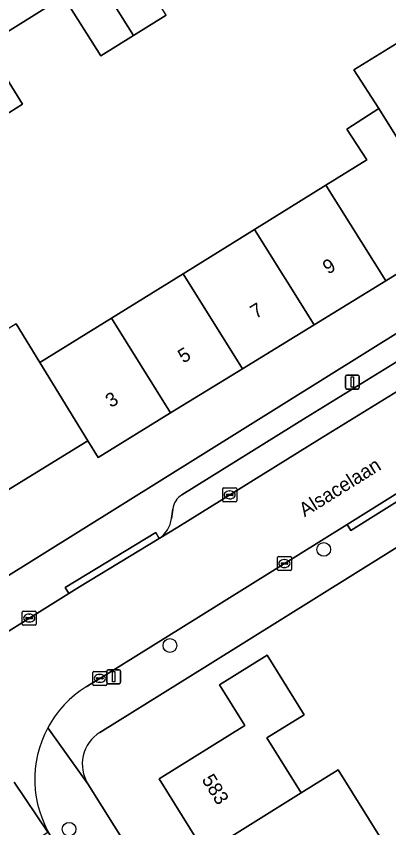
# Model space of a CAD drawing. Extents: x 157767 to 159172, y 387839 to 389425.
# Drawn here: x 158720.1 to 158746.7, y 388133.7 to 388191.6 of the extents above; entities that cross this region are included whole.
import ezdxf

# ---------------------------------------------------------------- set-up
doc = ezdxf.new("R2010")
doc.units = 0
for name, color, linetype in [('IMGEO_Boom', 7, 'Continuous'), ('IMGEO_Erf', 7, 'Continuous'), ('IMGEO_Kolk', 7, 'Continuous'), ('IMGEO_Lichtmast', 7, 'Continuous'), ('IMGEO_Muur', 7, 'Continuous'), ('IMGEO_Openbare_ruimte_label', 7, 'Continuous'), ('IMGEO_Pand', 7, 'Continuous'), ('IMGEO_Pand_nummerreeks', 7, 'Continuous'), ('IMGEO_Parkeervlak_open', 7, 'Continuous'), ('IMGEO_Rijbaan_lokaal_gesloten', 7, 'Continuous'), ('IMGEO_Rijbaan_lokaal_open', 7, 'Continuous'), ('IMGEO_Voetpad_open', 7, 'Continuous')]:
    doc.layers.add(name, color=color, linetype=linetype)

msp = doc.modelspace()

# ---------------------------------------------------------------- linework, layer by layer
at = {"layer": 'IMGEO_Boom'}
for centre in [(158742.03, 388153.561), (158731.046, 388146.702), (158723.845, 388133.586)]:
    msp.add_circle(centre, 0.489, dxfattribs=at)
at = {"layer": 'IMGEO_Erf'}
for points in [[(158761.692, 388194.688), (158765.881, 388187.864), (158760.624, 388184.637), (158755.413, 388181.438), (158752.713, 388179.781), (158754.565, 388176.764), (158752.076, 388175.236), (158748.692, 388173.159), (158748.271, 388173.845), (158746.449, 388172.727), (158741.336, 388169.588), (158736.223, 388166.45), (158731.091, 388163.3), (158725.924, 388160.128), (158725.19, 388161.323), (158725.067, 388161.247), (158716.251, 388155.836)], [(158743.681, 388183.556), (158745.961, 388185.032), (158744.167, 388187.803), (158749.433, 388191.036), (158751.173, 388188.231), (158756.335, 388191.4), (158754.508, 388194.376)], [(158730.775, 388191.695), (158728.443, 388190.242), (158726.101, 388188.784), (158723.453, 388193.037), (158717.902, 388189.558), (158720.525, 388185.346), (158718.236, 388183.92)], [(158720.07, 388169.662), (158721.758, 388166.913), (158726.866, 388170.077), (158731.981, 388173.244), (158737.082, 388176.403), (158742.182, 388179.562), (158745.097, 388181.367), (158743.681, 388183.556)], [(158650.367, 388165.452), (158650.337, 388165.203), (158715.951, 388149.492), (158768.176, 388182.052)], [(158771.779, 388169.011), (158765.822, 388165.297), (158752.075, 388156.726), (158733.718, 388145.281), (158728.372, 388141.947), (158726.036, 388140.491)], [(158733.566, 388131.912), (158730.278, 388137.186), (158736.388, 388140.995), (158734.585, 388143.889), (158737.98, 388146.006), (158740.626, 388141.763), (158737.975, 388140.111), (158740.422, 388136.185), (158743.064, 388137.832), (158746.254, 388132.715)], [(158725.193, 388136.821), (158765.78, 388072.075)]]:
    msp.add_lwpolyline(points, dxfattribs=at)
msp.add_arc((158727.448, 388138.235), 2.661, 122.03762, 212.08947, dxfattribs=at)
at = {"layer": 'IMGEO_Kolk'}
for p, q in [((158734.811, 388157.027), (158734.811, 388157.879)), ((158734.886, 388157.953), (158735.738, 388157.953)), ((158735.07, 388157.447), (158735.07, 388157.459)), ((158735.113, 388157.496), (158735.511, 388157.496)), ((158735.299, 388157.733), (158735.324, 388157.733)), ((158735.554, 388157.459), (158735.554, 388157.447)), ((158735.812, 388157.879), (158735.812, 388157.027)), ((158735.738, 388156.953), (158734.886, 388156.953)), ((158735.508, 388157.41), (158735.11, 388157.41)), ((158735.322, 388157.173), (158735.297, 388157.173)), ((158738.717, 388152.124), (158738.717, 388152.976)), ((158738.792, 388153.05), (158739.644, 388153.05)), ((158739.205, 388152.83), (158739.23, 388152.83)), ((158739.718, 388152.976), (158739.718, 388152.124)), ((158738.976, 388152.544), (158738.976, 388152.556)), ((158739.414, 388152.507), (158739.016, 388152.507)), ((158739.019, 388152.593), (158739.417, 388152.593)), ((158739.228, 388152.27), (158739.203, 388152.27)), ((158739.46, 388152.556), (158739.46, 388152.544)), ((158739.644, 388152.05), (158738.792, 388152.05)), ((158720.503, 388148.234), (158720.503, 388149.086)), ((158720.578, 388149.16), (158721.43, 388149.16)), ((158720.991, 388148.94), (158721.016, 388148.94)), ((158721.504, 388149.086), (158721.504, 388148.234)), ((158721.43, 388148.16), (158720.578, 388148.16)), ((158720.762, 388148.654), (158720.762, 388148.666)), ((158721.2, 388148.617), (158720.802, 388148.617)), ((158720.805, 388148.703), (158721.203, 388148.703)), ((158721.014, 388148.38), (158720.989, 388148.38)), ((158721.246, 388148.666), (158721.246, 388148.654)), ((158725.539, 388143.928), (158725.539, 388144.78)), ((158725.614, 388144.854), (158726.466, 388144.854)), ((158726.54, 388144.78), (158726.54, 388143.928)), ((158725.798, 388144.348), (158725.798, 388144.36)), ((158726.236, 388144.311), (158725.838, 388144.311)), ((158725.841, 388144.397), (158726.239, 388144.397)), ((158726.027, 388144.634), (158726.052, 388144.634)), ((158726.282, 388144.36), (158726.282, 388144.348)), ((158726.466, 388143.854), (158725.614, 388143.854)), ((158726.05, 388144.074), (158726.025, 388144.074))]:
    msp.add_line(p, q, dxfattribs=at)
for points in [[(158734.811, 388157.027), (158734.811, 388157.879)], [(158734.886, 388157.953), (158735.738, 388157.953)], [(158735.812, 388157.879), (158735.812, 388157.027)], [(158735.738, 388156.953), (158734.886, 388156.953)], [(158738.717, 388152.124), (158738.717, 388152.976)], [(158738.792, 388153.05), (158739.644, 388153.05)], [(158739.718, 388152.976), (158739.718, 388152.124)], [(158739.644, 388152.05), (158738.792, 388152.05)], [(158720.503, 388148.234), (158720.503, 388149.086)], [(158720.578, 388149.16), (158721.43, 388149.16)], [(158721.504, 388149.086), (158721.504, 388148.234)], [(158721.43, 388148.16), (158720.578, 388148.16)], [(158725.539, 388143.928), (158725.539, 388144.78)], [(158725.614, 388144.854), (158726.466, 388144.854)], [(158726.54, 388144.78), (158726.54, 388143.928)], [(158726.466, 388143.854), (158725.614, 388143.854)]]:
    msp.add_lwpolyline(points, dxfattribs=at)
for centre, radius, start, end in [((158734.888, 388157.877), 0.0765, 91.55205, 178.44795), ((158734.888, 388157.877), 0.0765, 91.55205, 178.44795), ((158735.11, 388157.456), 0.0403, 85.87752, 175.75265), ((158735.107, 388157.446), 0.0366, 178.93798, 274.71019), ((158735.511, 388157.453), 0.043, 264.86636, 352.45326), ((158735.515, 388157.458), 0.0386, 1.73085, 96.63898), ((158735.736, 388157.877), 0.0765, 1.55205, 88.44795), ((158735.736, 388157.877), 0.0765, 1.55205, 88.44795), ((158734.888, 388157.029), 0.0765, 181.55205, 268.44795), ((158734.888, 388157.029), 0.0765, 181.55205, 268.44795), ((158735.736, 388157.029), 0.0765, 271.55205, 358.44795), ((158735.736, 388157.029), 0.0765, 271.55205, 358.44795), ((158738.794, 388152.974), 0.0765, 91.55205, 178.44795), ((158738.794, 388152.974), 0.0765, 91.55205, 178.44795), ((158739.642, 388152.974), 0.0765, 1.55205, 88.44795), ((158739.642, 388152.974), 0.0765, 1.55205, 88.44795), ((158739.016, 388152.553), 0.0403, 85.87752, 175.75265), ((158739.013, 388152.543), 0.0366, 178.93798, 274.71019), ((158739.417, 388152.55), 0.043, 264.86636, 352.45326), ((158739.421, 388152.555), 0.0386, 1.73085, 96.63898), ((158738.794, 388152.126), 0.0765, 181.55205, 268.44795), ((158738.794, 388152.126), 0.0765, 181.55205, 268.44795), ((158739.642, 388152.126), 0.0765, 271.55205, 358.44795), ((158739.642, 388152.126), 0.0765, 271.55205, 358.44795), ((158720.58, 388149.084), 0.0765, 91.55205, 178.44795), ((158720.58, 388149.084), 0.0765, 91.55205, 178.44795), ((158721.428, 388149.084), 0.0765, 1.55205, 88.44795), ((158721.428, 388149.084), 0.0765, 1.55205, 88.44795), ((158720.58, 388148.236), 0.0765, 181.55205, 268.44795), ((158720.58, 388148.236), 0.0765, 181.55205, 268.44795), ((158720.802, 388148.663), 0.0403, 85.87752, 175.75265), ((158720.799, 388148.653), 0.0366, 178.93798, 274.71019), ((158721.203, 388148.66), 0.043, 264.86636, 352.45326), ((158721.207, 388148.665), 0.0386, 1.73085, 96.63898), ((158721.428, 388148.236), 0.0765, 271.55205, 358.44795), ((158721.428, 388148.236), 0.0765, 271.55205, 358.44795), ((158725.616, 388144.778), 0.0765, 91.55205, 178.44795), ((158725.616, 388144.778), 0.0765, 91.55205, 178.44795), ((158726.464, 388144.778), 0.0765, 1.55205, 88.44795), ((158726.464, 388144.778), 0.0765, 1.55205, 88.44795), ((158725.838, 388144.357), 0.0403, 85.87752, 175.75265), ((158725.835, 388144.347), 0.0366, 178.93798, 274.71019), ((158726.239, 388144.354), 0.043, 264.86636, 352.45326), ((158726.243, 388144.359), 0.0386, 1.73085, 96.63898), ((158725.616, 388143.93), 0.0765, 181.55205, 268.44795), ((158725.616, 388143.93), 0.0765, 181.55205, 268.44795), ((158726.464, 388143.93), 0.0765, 271.55205, 358.44795), ((158726.464, 388143.93), 0.0765, 271.55205, 358.44795)]:
    msp.add_arc(centre, radius, start, end, dxfattribs=at)
for centre, major_axis, ratio, start_param, end_param in [((158735.298, 388157.453), (-0.387, 0.002), 0.722429, 4.712389, 7.853982), ((158735.323, 388157.453), (-0.39, 0.002), 0.717154, 1.570796, 4.712389), ((158739.204, 388152.55), (-0.387, 0.002), 0.722429, 4.712389, 7.853982), ((158739.229, 388152.55), (-0.39, 0.002), 0.717154, 1.570796, 4.712389), ((158720.99, 388148.66), (-0.387, 0.002), 0.722429, 4.712389, 7.853982), ((158721.015, 388148.66), (-0.39, 0.002), 0.717154, 1.570796, 4.712389), ((158726.026, 388144.354), (-0.387, 0.002), 0.722429, 4.712389, 7.853982), ((158726.051, 388144.354), (-0.39, 0.002), 0.717154, 1.570796, 4.712389)]:
    msp.add_ellipse(centre, major_axis=major_axis, ratio=ratio, start_param=start_param, end_param=end_param, dxfattribs=at)
at = {"layer": 'IMGEO_Lichtmast'}
for p, q in [((158743.569, 388165.107), (158743.569, 388165.907)), ((158743.569, 388165.907), (158743.569, 388165.107)), ((158743.669, 388166.007), (158744.459, 388166.007)), ((158744.459, 388166.007), (158743.669, 388166.007)), ((158744.559, 388165.907), (158744.559, 388165.107)), ((158744.559, 388165.107), (158744.559, 388165.907)), ((158744.459, 388165.007), (158743.669, 388165.007)), ((158743.669, 388165.007), (158744.459, 388165.007)), ((158726.536, 388144.076), (158726.536, 388144.876)), ((158726.536, 388144.876), (158726.536, 388144.076)), ((158726.636, 388144.976), (158727.426, 388144.976)), ((158727.426, 388144.976), (158726.636, 388144.976)), ((158727.526, 388144.876), (158727.526, 388144.076)), ((158727.526, 388144.076), (158727.526, 388144.876)), ((158727.426, 388143.976), (158726.636, 388143.976)), ((158726.636, 388143.976), (158727.426, 388143.976))]:
    msp.add_line(p, q, dxfattribs=at)
for points in [[(158743.989, 388165.882), (158744.139, 388165.882), (158744.139, 388165.132), (158743.989, 388165.132), (158743.989, 388165.882)], [(158726.956, 388144.851), (158727.106, 388144.851), (158727.106, 388144.101), (158726.956, 388144.101), (158726.956, 388144.851)]]:
    msp.add_lwpolyline(points, dxfattribs=at)
for centre, start, end in [((158743.669, 388165.907), 90, 180), ((158743.669, 388165.907), 90, 180), ((158744.459, 388165.907), 0, 90), ((158744.459, 388165.907), 360, 90), ((158743.669, 388165.107), 180, 270), ((158743.669, 388165.107), 180, 270), ((158744.459, 388165.107), 270, 0), ((158744.459, 388165.107), 270, 0), ((158726.636, 388144.876), 90, 180), ((158726.636, 388144.876), 90, 180), ((158727.426, 388144.876), 0, 90), ((158727.426, 388144.876), 360, 90), ((158726.636, 388144.076), 180, 270), ((158726.636, 388144.076), 180, 270), ((158727.426, 388144.076), 270, 0), ((158727.426, 388144.076), 270, 0)]:
    msp.add_arc(centre, 0.1, start, end, dxfattribs=at)
at = {"layer": 'IMGEO_Muur'}
msp.add_lwpolyline([(158733.718, 388145.281), (158728.372, 388141.947)], dxfattribs=at)
at = {"layer": 'IMGEO_Pand'}
for points in [[(158728.443, 388190.242), (158730.775, 388191.695), (158728.127, 388195.948), (158725.79, 388194.492)], [(158728.443, 388190.242), (158725.79, 388194.492), (158723.453, 388193.037), (158726.101, 388188.784)], [(158745.961, 388185.032), (158752.076, 388175.236), (158754.565, 388176.764), (158752.713, 388179.781), (158755.413, 388181.438), (158751.173, 388188.231), (158749.433, 388191.036), (158744.167, 388187.803)], [(158715.611, 388188.131), (158718.236, 388183.92), (158720.525, 388185.346), (158717.902, 388189.558)], [(158745.961, 388185.032), (158743.681, 388183.556), (158745.097, 388181.367), (158742.182, 388179.562), (158746.449, 388172.727), (158748.271, 388173.845), (158748.692, 388173.159), (158752.076, 388175.236)], [(158746.449, 388172.727), (158742.182, 388179.562), (158737.082, 388176.403), (158741.336, 388169.588)], [(158737.082, 388176.403), (158731.981, 388173.244), (158736.223, 388166.45), (158741.336, 388169.588)], [(158726.866, 388170.077), (158731.091, 388163.3), (158736.223, 388166.45), (158731.981, 388173.244)], [(158721.758, 388166.913), (158720.07, 388169.662), (158714.573, 388166.287), (158713.927, 388167.33), (158711.467, 388165.807), (158712.066, 388162.649), (158715.824, 388156.53), (158716.251, 388155.836), (158725.067, 388161.247), (158725.19, 388161.323)], [(158726.866, 388170.077), (158721.758, 388166.913), (158725.19, 388161.323), (158725.924, 388160.128), (158731.091, 388163.3)], [(158740.422, 388136.185), (158737.975, 388140.111), (158740.626, 388141.763), (158737.98, 388146.006), (158734.585, 388143.889), (158736.388, 388140.995), (158730.278, 388137.186), (158733.566, 388131.912)], [(158740.422, 388136.185), (158733.566, 388131.912), (158736.756, 388126.794), (158743.612, 388131.068), (158746.254, 388132.715), (158743.064, 388137.832)]]:
    msp.add_lwpolyline(points, close=True, dxfattribs=at)
at = {"layer": 'IMGEO_Parkeervlak_open'}
for points in [[(158730.286, 388154.349), (158731.615, 388155.157), (158741.723, 388161.435), (158752.849, 388168.293), (158761.897, 388173.962), (158770.871, 388179.63)], [(158767.748, 388179.761), (158760.94, 388175.488), (158751.898, 388169.823), (158740.775, 388162.967), (158731.897, 388157.453)], [(158731.247, 388156.441), (158731.16, 388155.759)]]:
    msp.add_lwpolyline(points, dxfattribs=at)
for centre, radius, start, end in [((158732.639, 388156.262), 1.404, 121.91626, 172.65908), ((158729.176, 388156.013), 2, 303.70666, 352.70725)]:
    msp.add_arc(centre, radius, start, end, dxfattribs=at)
at = {"layer": 'IMGEO_Rijbaan_lokaal_gesloten'}
msp.add_lwpolyline([(158717.852, 388129.025), (158725.178, 388117.248), (158731.411, 388107.326), (158740.295, 388093.103), (158749.242, 388078.803), (158749.797, 388077.971), (158750.922, 388076.09), (158754.085, 388078.005), (158751.334, 388082.198), (158745.833, 388091.038), (158737.528, 388104.244), (158727.681, 388119.9), (158720.109, 388131.939), (158722.336, 388133.375), (158719.936, 388136.946)], dxfattribs=at)
at = {"layer": 'IMGEO_Rijbaan_lokaal_open'}
for points in [[(158717.902, 388189.558), (158723.453, 388193.037)], [(158776.519, 388171.716), (158771.15, 388179.789), (158770.871, 388179.63), (158761.897, 388173.962), (158752.849, 388168.293), (158741.723, 388161.435), (158731.615, 388155.157), (158730.286, 388154.349), (158724.598, 388150.885), (158723.834, 388150.412), (158718.207, 388146.927), (158717.535, 388146.511), (158715.318, 388145.265)], [(158725.067, 388143.751), (158726.465, 388144.619), (158733.082, 388148.73), (158743.691, 388155.337), (158746.928, 388157.353), (158750.199, 388159.405)], [(158719.936, 388136.946), (158722.336, 388133.375), (158722.572, 388133.024)]]:
    msp.add_lwpolyline(points, dxfattribs=at)
for centre, radius, start, end in [((158729.194, 388137.13), 7.802, 121.93521, 151.72223), ((158729.185, 388137.14), 7.789, 151.7555, 211.90044)]:
    msp.add_arc(centre, radius, start, end, dxfattribs=at)
at = {"layer": 'IMGEO_Voetpad_open'}
for points in [[(158768.176, 388182.052), (158715.951, 388149.492), (158718.207, 388146.927), (158723.834, 388150.412)], [(158731.897, 388157.453), (158740.775, 388162.967), (158751.898, 388169.823), (158760.94, 388175.488), (158767.748, 388179.761)], [(158770.596, 388172.199), (158750.199, 388159.405), (158750.463, 388158.981), (158743.955, 388154.913), (158743.691, 388155.337), (158733.082, 388148.73), (158726.465, 388144.619), (158725.067, 388143.751)], [(158726.036, 388140.491), (158728.372, 388141.947), (158733.718, 388145.281), (158752.075, 388156.726)], [(158731.16, 388155.759), (158731.247, 388156.441)], [(158723.834, 388150.412), (158723.575, 388150.839), (158730.027, 388154.775), (158730.286, 388154.349)], [(158725.193, 388136.821), (158722.323, 388140.826)], [(158722.323, 388140.826), (158725.193, 388136.821)], [(158763.264, 388070.83), (158765.78, 388072.075), (158725.193, 388136.821)]]:
    msp.add_lwpolyline(points, dxfattribs=at)
for points in [[(158743.691, 388155.337), (158743.955, 388154.913), (158750.463, 388158.981), (158750.199, 388159.405), (158746.928, 388157.353)], [(158730.286, 388154.349), (158730.027, 388154.775), (158723.575, 388150.839), (158723.834, 388150.412), (158724.598, 388150.885)]]:
    msp.add_lwpolyline(points, close=True, dxfattribs=at)
for centre, radius, start, end in [((158732.639, 388156.262), 1.404, 121.91626, 172.65908), ((158729.176, 388156.013), 2, 303.70666, 352.70725), ((158729.194, 388137.13), 7.802, 121.93521, 151.72223), ((158729.185, 388137.14), 7.789, 151.7555, 211.90044), ((158727.448, 388138.235), 2.661, 122.03762, 212.08947)]:
    msp.add_arc(centre, radius, start, end, dxfattribs=at)

# ---------------------------------------------------------------- texts
at = {"layer": 'IMGEO_Openbare_ruimte_label'}
msp.add_text('Alsacelaan', height=1, rotation=31.92646, dxfattribs=at).set_placement((158740.658, 388155.849))
at = {"layer": 'IMGEO_Pand_nummerreeks'}
for s, rotation, p in [('9', 31.54216, (158742.342, 388173.162)), ('7', 31.54133, (158737.172, 388169.988)), ('5', 31.54216, (158732.002, 388166.816)), ('3', 31.54133, (158726.832, 388163.641)), ('583', 301.93974, (158733.282, 388137.13))]:
    msp.add_text(s, height=1, rotation=rotation, dxfattribs=at).set_placement(p)

doc.saveas('drawing.dxf')
